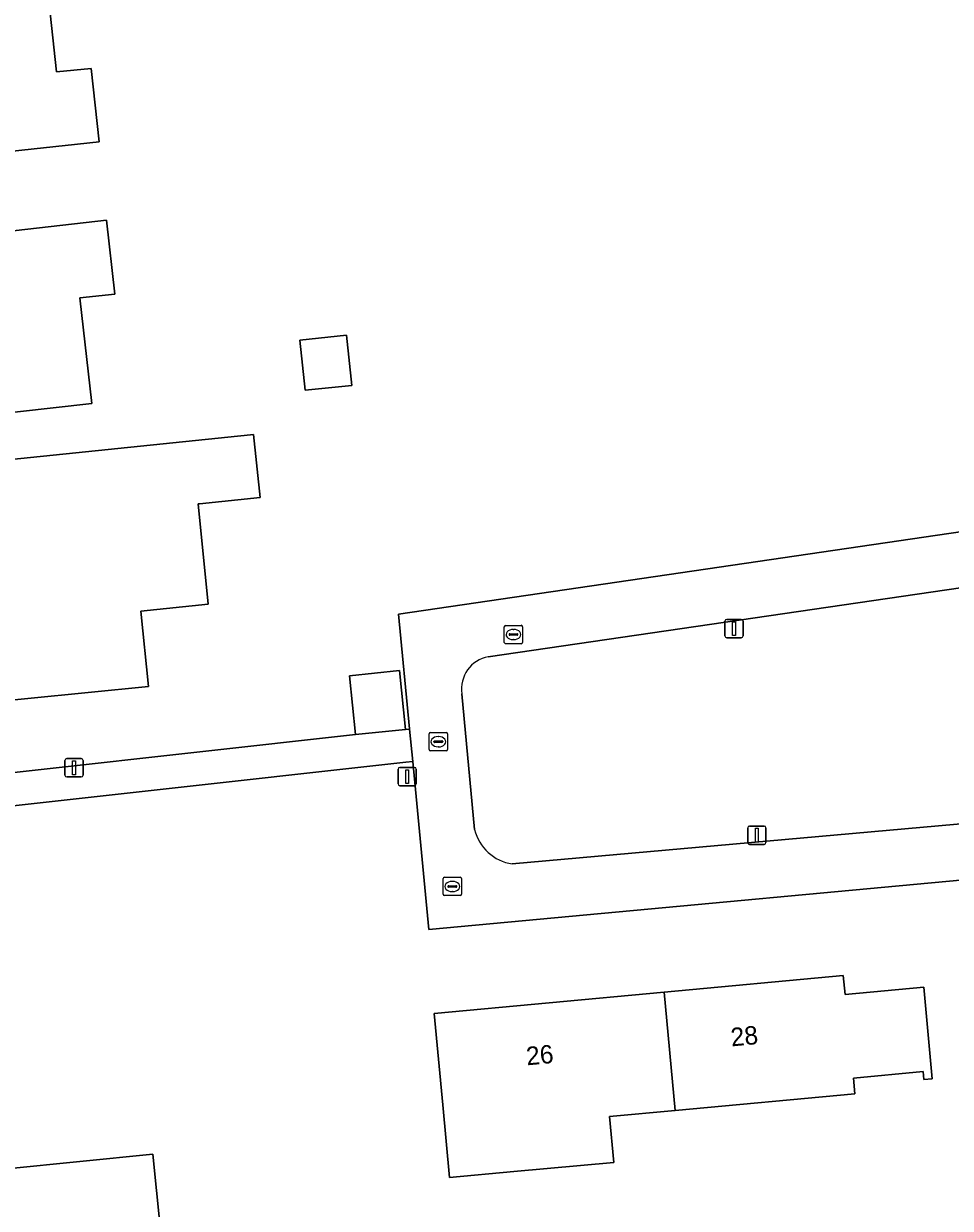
# Model space of a CAD drawing. Extents: x 162661 to 163484, y 380247 to 381230.
# Drawn here: x 163049.7 to 163100.1, y 380565.8 to 380630.3 of the extents above; entities that cross this region are included whole.
import ezdxf

# ---------------------------------------------------------------- set-up
doc = ezdxf.new("R2010")
doc.units = 0
for name, color, linetype in [('IMGEO_Brandkraan', 7, 'Continuous'), ('IMGEO_Erf', 7, 'Continuous'), ('IMGEO_Groenvoorziening', 7, 'Continuous'), ('IMGEO_Lichtmast', 7, 'Continuous'), ('IMGEO_Pand', 7, 'Continuous'), ('IMGEO_Pand_nummerreeks', 7, 'Continuous'), ('IMGEO_Rijbaan_lokaal_open', 7, 'Continuous'), ('IMGEO_Rioolput', 7, 'Continuous'), ('IMGEO_Voetpad_open', 7, 'Continuous')]:
    doc.layers.add(name, color=color, linetype=linetype)

msp = doc.modelspace()

# ---------------------------------------------------------------- linework, layer by layer
at = {"layer": 'IMGEO_Brandkraan'}
for p, q in [((163071.834, 380591.744), (163072.686, 380591.744)), ((163071.759, 380590.818), (163071.759, 380591.67)), ((163072.018, 380591.238), (163072.018, 380591.25)), ((163072.456, 380591.201), (163072.058, 380591.201)), ((163072.061, 380591.287), (163072.459, 380591.287)), ((163072.247, 380591.524), (163072.272, 380591.524)), ((163072.502, 380591.25), (163072.502, 380591.238)), ((163072.76, 380591.67), (163072.76, 380590.818)), ((163072.686, 380590.744), (163071.834, 380590.744)), ((163072.27, 380590.964), (163072.245, 380590.964))]:
    msp.add_line(p, q, dxfattribs=at)
for points in [[(163071.834, 380591.744), (163072.686, 380591.744)], [(163071.759, 380590.818), (163071.759, 380591.67)], [(163072.76, 380591.67), (163072.76, 380590.818)], [(163072.686, 380590.744), (163071.834, 380590.744)]]:
    msp.add_lwpolyline(points, dxfattribs=at)
for centre, radius, start, end in [((163071.836, 380591.668), 0.0765, 91.55205, 178.44795), ((163071.836, 380591.668), 0.0765, 91.55205, 178.44795), ((163072.684, 380591.668), 0.0765, 1.55205, 88.44795), ((163072.684, 380591.668), 0.0765, 1.55205, 88.44795), ((163072.058, 380591.247), 0.0403, 85.87752, 175.75265), ((163072.055, 380591.237), 0.0366, 178.93798, 274.71019), ((163072.459, 380591.244), 0.043, 264.86636, 352.45326), ((163072.463, 380591.249), 0.0386, 1.73085, 96.63898), ((163071.836, 380590.82), 0.0765, 181.55205, 268.44795), ((163071.836, 380590.82), 0.0765, 181.55205, 268.44795), ((163072.684, 380590.82), 0.0765, 271.55205, 358.44795), ((163072.684, 380590.82), 0.0765, 271.55205, 358.44795)]:
    msp.add_arc(centre, radius, start, end, dxfattribs=at)
for centre, major_axis, ratio, start_param, end_param in [((163072.246, 380591.244), (-0.387, 0.002), 0.722429, 4.712389, 7.853982), ((163072.271, 380591.244), (-0.39, 0.002), 0.717154, 1.570796, 4.712389)]:
    msp.add_ellipse(centre, major_axis=major_axis, ratio=ratio, start_param=start_param, end_param=end_param, dxfattribs=at)
at = {"layer": 'IMGEO_Erf'}
for points in [[(163104.464, 380649.238), (163101.514, 380648.96), (163064.825, 380645.41), (163064.179, 380655.165), (163063.957, 380655.14), (163037.446, 380652.111), (163041.973, 380588.769), (163067.753, 380591.633), (163067.425, 380594.839), (163070.153, 380595.118), (163070.481, 380591.912), (163070.696, 380591.934), (163070.695, 380591.946), (163070.09, 380598.191), (163102.911, 380602.998), (163106.144, 380603.482), (163108.863, 380603.734), (163108.827, 380604.097)], [(163053.779, 380623.892), (163048.907, 380623.369), (163043.936, 380622.835), (163042.887, 380632.592), (163047.858, 380633.126), (163050.841, 380633.446), (163051.458, 380627.709), (163053.348, 380627.899)], [(163053.38, 380609.656), (163045.43, 380608.763), (163044.335, 380618.51), (163054.191, 380619.638), (163054.643, 380615.614), (163052.735, 380615.399)], [(163064.724, 380613.105), (163067.267, 380613.367), (163067.548, 380610.637), (163065.006, 380610.375)], [(163062.029, 380607.949), (163062.196, 380607.967), (163062.55, 380604.54), (163059.253, 380604.2), (163059.171, 380604.191), (163059.728, 380598.733), (163056.052, 380598.358), (163056.471, 380594.258), (163046.605, 380593.261), (163045.272, 380606.22)], [(163110.709, 380584.612), (163108.503, 380584.435), (163071.752, 380581.021), (163070.867, 380590.166), (163070.497, 380590.125), (163042.074, 380586.977), (163046.628, 380523.045), (163076.447, 380526.277), (163075.37, 380533.477), (163111.52, 380538.838), (163114.801, 380539.349), (163114.529, 380544.063)], [(163085.154, 380571.175), (163081.583, 380570.845), (163081.814, 380568.345), (163076.365, 380567.842), (163072.869, 380567.519), (163072.503, 380571.475), (163072.042, 380576.453), (163084.559, 380577.61), (163094.32, 380578.513), (163094.415, 380577.492), (163098.697, 380577.888), (163099.159, 380572.901), (163098.711, 380572.86), (163098.671, 380573.288), (163094.868, 380572.936), (163094.947, 380572.081)], [(163057.286, 380563.044), (163059.267, 380563.241), (163059.669, 380559.19), (163057.807, 380559.005), (163057.982, 380557.233), (163053.633, 380556.801), (163053.457, 380558.574), (163049.726, 380558.204), (163048.754, 380567.994), (163056.716, 380568.784)]]:
    msp.add_lwpolyline(points, close=True, dxfattribs=at)
at = {"layer": 'IMGEO_Groenvoorziening'}
for points in [[(163076.287, 380584.592), (163107.852, 380587.415), (163108.009, 380587.432), (163107.973, 380587.808), (163106.794, 380600.058), (163106.765, 380600.479), (163103.191, 380599.978), (163074.982, 380595.872)], [(163073.543, 380593.846), (163074.237, 380586.467)]]:
    msp.add_lwpolyline(points, dxfattribs=at)
for centre, radius, start, end in [((163075.315, 380594.112), 1.791, 100.69744, 188.53275), ((163076.651, 380587.048), 2.482, 193.52666, 261.57913)]:
    msp.add_arc(centre, radius, start, end, dxfattribs=at)
at = {"layer": 'IMGEO_Lichtmast'}
for p, q in [((163087.872, 380597.001), (163087.872, 380597.801)), ((163087.872, 380597.801), (163087.872, 380597.001)), ((163087.972, 380597.901), (163088.762, 380597.901)), ((163088.762, 380597.901), (163087.972, 380597.901)), ((163088.862, 380597.801), (163088.862, 380597.001)), ((163088.862, 380597.001), (163088.862, 380597.801)), ((163088.762, 380596.901), (163087.972, 380596.901)), ((163087.972, 380596.901), (163088.762, 380596.901)), ((163051.92, 380589.425), (163051.92, 380590.225)), ((163051.92, 380590.225), (163051.92, 380589.425)), ((163052.02, 380590.325), (163052.81, 380590.325)), ((163052.81, 380590.325), (163052.02, 380590.325)), ((163052.91, 380590.225), (163052.91, 380589.425)), ((163052.91, 380589.425), (163052.91, 380590.225)), ((163070.171, 380589.845), (163070.961, 380589.845)), ((163070.961, 380589.845), (163070.171, 380589.845)), ((163052.81, 380589.325), (163052.02, 380589.325)), ((163052.02, 380589.325), (163052.81, 380589.325)), ((163070.071, 380588.945), (163070.071, 380589.745)), ((163070.071, 380589.745), (163070.071, 380588.945)), ((163071.061, 380589.745), (163071.061, 380588.945)), ((163071.061, 380588.945), (163071.061, 380589.745)), ((163070.961, 380588.845), (163070.171, 380588.845)), ((163070.171, 380588.845), (163070.961, 380588.845)), ((163089.116, 380585.754), (163089.116, 380586.554)), ((163089.116, 380586.554), (163089.116, 380585.754)), ((163089.216, 380586.654), (163090.006, 380586.654)), ((163090.006, 380586.654), (163089.216, 380586.654)), ((163090.106, 380586.554), (163090.106, 380585.754)), ((163090.106, 380585.754), (163090.106, 380586.554)), ((163090.006, 380585.654), (163089.216, 380585.654)), ((163089.216, 380585.654), (163090.006, 380585.654))]:
    msp.add_line(p, q, dxfattribs=at)
for points in [[(163088.292, 380597.776), (163088.442, 380597.776), (163088.442, 380597.026), (163088.292, 380597.026), (163088.292, 380597.776)], [(163052.34, 380590.2), (163052.49, 380590.2), (163052.49, 380589.45), (163052.34, 380589.45), (163052.34, 380590.2)], [(163070.491, 380589.72), (163070.641, 380589.72), (163070.641, 380588.97), (163070.491, 380588.97), (163070.491, 380589.72)], [(163089.536, 380586.529), (163089.686, 380586.529), (163089.686, 380585.779), (163089.536, 380585.779), (163089.536, 380586.529)]]:
    msp.add_lwpolyline(points, dxfattribs=at)
for centre, start, end in [((163087.972, 380597.801), 90, 180), ((163087.972, 380597.801), 90, 180), ((163088.762, 380597.801), 0, 90), ((163088.762, 380597.801), 360, 90), ((163087.972, 380597.001), 180, 270), ((163087.972, 380597.001), 180, 270), ((163088.762, 380597.001), 270, 0), ((163088.762, 380597.001), 270, 0), ((163052.02, 380590.225), 90, 180), ((163052.02, 380590.225), 90, 180), ((163052.81, 380590.225), 0, 90), ((163052.81, 380590.225), 360, 90), ((163070.171, 380589.745), 90, 180), ((163070.171, 380589.745), 90, 180), ((163070.961, 380589.745), 0, 90), ((163070.961, 380589.745), 360, 90), ((163052.02, 380589.425), 180, 270), ((163052.02, 380589.425), 180, 270), ((163052.81, 380589.425), 270, 0), ((163052.81, 380589.425), 270, 0), ((163070.171, 380588.945), 180, 270), ((163070.171, 380588.945), 180, 270), ((163070.961, 380588.945), 270, 0), ((163070.961, 380588.945), 270, 0), ((163089.216, 380586.554), 90, 180), ((163089.216, 380586.554), 90, 180), ((163090.006, 380586.554), 0, 90), ((163090.006, 380586.554), 360, 90), ((163089.216, 380585.754), 180, 270), ((163089.216, 380585.754), 180, 270), ((163090.006, 380585.754), 270, 0), ((163090.006, 380585.754), 270, 0)]:
    msp.add_arc(centre, 0.1, start, end, dxfattribs=at)
at = {"layer": 'IMGEO_Pand'}
for points in [[(163043.936, 380622.835), (163048.907, 380623.369), (163053.779, 380623.892), (163053.348, 380627.899), (163051.458, 380627.709), (163050.841, 380633.446), (163047.858, 380633.126), (163042.887, 380632.592)], [(163045.43, 380608.763), (163053.38, 380609.656), (163052.735, 380615.399), (163054.643, 380615.614), (163054.191, 380619.638), (163044.335, 380618.51)], [(163064.724, 380613.105), (163065.006, 380610.375), (163067.548, 380610.637), (163067.267, 380613.367)], [(163059.171, 380604.191), (163059.253, 380604.2), (163062.55, 380604.54), (163062.196, 380607.967), (163062.029, 380607.949), (163045.272, 380606.22), (163046.605, 380593.261), (163056.471, 380594.258), (163056.052, 380598.358), (163059.728, 380598.733)], [(163067.425, 380594.839), (163067.753, 380591.633), (163070.481, 380591.912), (163070.153, 380595.118)], [(163085.154, 380571.175), (163094.947, 380572.081), (163094.868, 380572.936), (163098.671, 380573.288), (163098.711, 380572.86), (163099.159, 380572.901), (163098.697, 380577.888), (163094.415, 380577.492), (163094.32, 380578.513), (163084.559, 380577.61)], [(163085.154, 380571.175), (163084.559, 380577.61), (163072.042, 380576.453), (163072.503, 380571.475), (163072.869, 380567.519), (163076.365, 380567.842), (163081.814, 380568.345), (163081.583, 380570.845)], [(163059.267, 380563.241), (163057.286, 380563.044), (163056.716, 380568.784), (163048.754, 380567.994), (163049.726, 380558.204), (163053.457, 380558.574), (163053.633, 380556.801), (163057.982, 380557.233), (163057.807, 380559.005), (163059.669, 380559.19)]]:
    msp.add_lwpolyline(points, close=True, dxfattribs=at)
at = {"layer": 'IMGEO_Rijbaan_lokaal_open'}
for points in [[(163074.982, 380595.872), (163103.191, 380599.978), (163106.765, 380600.479), (163106.144, 380603.482), (163102.911, 380602.998), (163070.09, 380598.191), (163070.695, 380591.946), (163070.696, 380591.934), (163070.867, 380590.166), (163071.752, 380581.021), (163108.503, 380584.435), (163108.009, 380587.432), (163107.852, 380587.415), (163076.287, 380584.592)], [(163074.237, 380586.467), (163073.543, 380593.846)]]:
    msp.add_lwpolyline(points, dxfattribs=at)
for centre, radius, start, end in [((163075.315, 380594.112), 1.791, 100.69744, 188.53275), ((163076.651, 380587.048), 2.482, 193.52666, 261.57913)]:
    msp.add_arc(centre, radius, start, end, dxfattribs=at)
at = {"layer": 'IMGEO_Rioolput'}
for p, q in [((163075.927, 380597.579), (163076.779, 380597.579)), ((163075.852, 380596.653), (163075.852, 380597.505)), ((163076.111, 380597.073), (163076.111, 380597.085)), ((163076.549, 380597.036), (163076.151, 380597.036)), ((163076.154, 380597.122), (163076.552, 380597.122)), ((163076.34, 380597.359), (163076.365, 380597.359)), ((163076.595, 380597.085), (163076.595, 380597.073)), ((163076.853, 380597.505), (163076.853, 380596.653)), ((163076.779, 380596.579), (163075.927, 380596.579)), ((163076.363, 380596.799), (163076.338, 380596.799)), ((163072.524, 380582.938), (163072.524, 380583.79)), ((163072.599, 380583.864), (163073.451, 380583.864)), ((163072.783, 380583.358), (163072.783, 380583.37)), ((163072.826, 380583.407), (163073.224, 380583.407)), ((163073.012, 380583.644), (163073.037, 380583.644)), ((163073.267, 380583.37), (163073.267, 380583.358)), ((163073.525, 380583.79), (163073.525, 380582.938)), ((163073.451, 380582.864), (163072.599, 380582.864)), ((163073.221, 380583.321), (163072.823, 380583.321)), ((163073.035, 380583.084), (163073.01, 380583.084))]:
    msp.add_line(p, q, dxfattribs=at)
for points in [[(163075.927, 380597.579), (163076.779, 380597.579)], [(163075.852, 380596.653), (163075.852, 380597.505)], [(163076.853, 380597.505), (163076.853, 380596.653)], [(163076.779, 380596.579), (163075.927, 380596.579)], [(163072.524, 380582.938), (163072.524, 380583.79)], [(163072.599, 380583.864), (163073.451, 380583.864)], [(163073.525, 380583.79), (163073.525, 380582.938)], [(163073.451, 380582.864), (163072.599, 380582.864)]]:
    msp.add_lwpolyline(points, dxfattribs=at)
for centre, radius, start, end in [((163075.929, 380597.503), 0.0765, 91.55205, 178.44795), ((163075.929, 380597.503), 0.0765, 91.55205, 178.44795), ((163076.777, 380597.503), 0.0765, 1.55205, 88.44795), ((163076.777, 380597.503), 0.0765, 1.55205, 88.44795), ((163076.151, 380597.082), 0.0403, 85.87752, 175.75265), ((163076.148, 380597.072), 0.0366, 178.93798, 274.71019), ((163076.552, 380597.079), 0.043, 264.86636, 352.45326), ((163076.556, 380597.084), 0.0386, 1.73085, 96.63898), ((163075.929, 380596.655), 0.0765, 181.55205, 268.44795), ((163075.929, 380596.655), 0.0765, 181.55205, 268.44795), ((163076.777, 380596.655), 0.0765, 271.55205, 358.44795), ((163076.777, 380596.655), 0.0765, 271.55205, 358.44795), ((163072.601, 380583.788), 0.0765, 91.55205, 178.44795), ((163072.601, 380583.788), 0.0765, 91.55205, 178.44795), ((163072.823, 380583.367), 0.0403, 85.87752, 175.75265), ((163072.82, 380583.357), 0.0366, 178.93798, 274.71019), ((163073.224, 380583.364), 0.043, 264.86636, 352.45326), ((163073.228, 380583.369), 0.0386, 1.73085, 96.63898), ((163073.449, 380583.788), 0.0765, 1.55205, 88.44795), ((163073.449, 380583.788), 0.0765, 1.55205, 88.44795), ((163072.601, 380582.94), 0.0765, 181.55205, 268.44795), ((163072.601, 380582.94), 0.0765, 181.55205, 268.44795), ((163073.449, 380582.94), 0.0765, 271.55205, 358.44795), ((163073.449, 380582.94), 0.0765, 271.55205, 358.44795)]:
    msp.add_arc(centre, radius, start, end, dxfattribs=at)
for centre, major_axis, ratio, start_param, end_param in [((163076.339, 380597.079), (-0.387, 0.002), 0.722429, 4.712389, 7.853982), ((163076.364, 380597.079), (-0.39, 0.002), 0.717154, 1.570796, 4.712389), ((163073.011, 380583.364), (-0.387, 0.002), 0.722429, 4.712389, 7.853982), ((163073.036, 380583.364), (-0.39, 0.002), 0.717154, 1.570796, 4.712389)]:
    msp.add_ellipse(centre, major_axis=major_axis, ratio=ratio, start_param=start_param, end_param=end_param, dxfattribs=at)
at = {"layer": 'IMGEO_Voetpad_open'}
for points in [[(163070.497, 380590.125), (163070.867, 380590.166), (163070.696, 380591.934), (163070.481, 380591.912), (163067.753, 380591.633), (163041.973, 380588.769), (163037.446, 380652.111), (163063.957, 380655.14), (163064.179, 380655.165), (163064.055, 380657.039), (163063.757, 380657.004), (163037.315, 380653.943), (163032.944, 380715.524), (163058.632, 380719.002), (163058.898, 380719.038), (163058.785, 380720.911), (163058.503, 380720.872), (163032.814, 380717.345), (163030.493, 380750), (163029.443, 380764.786), (163028.665, 380775.858), (163028.488, 380778.563), (163028.12, 380778.882)], [(163051.286, 380456.864), (163048.191, 380500), (163046.661, 380521.315), (163076.715, 380524.487), (163076.447, 380526.277), (163046.628, 380523.045), (163042.074, 380586.977), (163070.497, 380590.125)]]:
    msp.add_lwpolyline(points, dxfattribs=at)

# ---------------------------------------------------------------- texts
at = {"layer": 'IMGEO_Pand_nummerreeks'}
for s, p in [('28', (163088.233, 380574.656)), ('26', (163077.091, 380573.625))]:
    msp.add_text(s, height=1, rotation=5.283, dxfattribs=at).set_placement(p)

doc.saveas('drawing.dxf')
